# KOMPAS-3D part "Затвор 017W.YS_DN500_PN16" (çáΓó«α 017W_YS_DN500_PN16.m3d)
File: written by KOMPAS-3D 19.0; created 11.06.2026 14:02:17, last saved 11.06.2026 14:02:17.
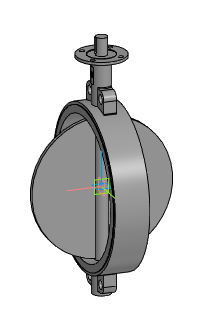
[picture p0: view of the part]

Document properties: Автор: Евгений; Полное имя файла: Z:\3.Личные\kachalov\001_3d для проектировщиков\x.x Тип 017W.Y(S) Затвор дисковый поворотный межфланцевый\_stp_Затвор 017W.YS_DN32-DN1200\Затвор 017W_YS_DN500_PN16.m3d

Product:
- Part/product: Затвор 017W.YS_DN500_PN16

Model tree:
1. Операция без истории:1  (labels: Затвор 017W.YS_DN500_PN16)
